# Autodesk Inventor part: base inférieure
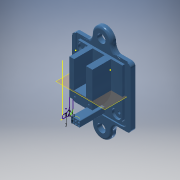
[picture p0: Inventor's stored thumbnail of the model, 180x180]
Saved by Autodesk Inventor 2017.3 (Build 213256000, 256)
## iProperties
Part Number: base inférieure
Material: Générique
Document SubType Name: Modeling
Designer: ficho
Density: 1 g/cm^3
Appearance: Pervenche
Author: ficho
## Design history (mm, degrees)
sketch "Esquisse1"
  geometry: L1 (4.5, -5.45)-(-4.5, -5.45) reference; L2 (4.5, 5.45)-(4.5, -5.45) reference; L3 (-4.5, 5.45)-(4.5, 5.45) reference; L4 (-4.5, -5.45)-(-4.5, 5.45) reference; L5 (-1.95, -7.7)-(4.55, -7.7) reference; L6 (-2.55, -9.12)-(-2.55, -8.3) reference; L7 (-2.096, -9.759)-(-2.308, -9.601) reference; L8 (-1.935, -10.8)-(-1.935, -10.08) reference; L9 (3.935, -11.4)-(-1.335, -11.4) reference; L10 (4.535, -10.08)-(4.535, -10.8) reference; L11 (4.908, -9.601)-(4.696, -9.759) reference; L12 (5.15, -8.3)-(5.15, -9.12) reference; L13 (-1.95, -8)-(4.55, -8) reference; L14 (4.85, -8.3)-(4.85, -9.12) reference; L15 (4.729, -9.361)-(4.517, -9.518) reference; L16 (4.235, -10.08)-(4.235, -10.8) reference; L17 (3.935, -11.1)-(-1.335, -11.1) reference; L18 (-1.635, -10.8)-(-1.635, -10.08) reference; L19 (-1.917, -9.518)-(-2.129, -9.361) reference; L20 (-2.25, -9.12)-(-2.25, -8.3) reference; L21 (-17.7, 15.45)-(20.2, 15.45); L22 (20.2, 15.45)-(20.2, -5.45); L23 (-17.7, -5.45)-(-17.7, 15.45); L24 (-5, -5.45)-(-17.7, -5.45); L25 (5, -5.45)-(20.2, -5.45); L26 (-5, -5.45)-(-5, 5.95); L27 (5, 5.95)-(5, -5.45); L28 (-5, 5.95)-(4.235, 5.95); L29 (4.5, 5.95)-(5, 5.95); L30 (-1.635, -5.95)-(-1.935, -5.95); L31 (-2.25, -5.95)-(-2.55, -5.95); L32 (5, -5.95)-(4.85, -5.95); L33 (4.535, -5.95)-(4.5, -5.95); L34 (4.5, 5.95)-(4.235, 5.95); C1 r 3.15 at (0, 0.95) reference; A1 r 0.6 centre (4.55, -8.3) between (5.15, -8.3) and (4.55, -7.7) reference; A2 r 0.6 centre (-1.95, -8.3) between (-1.95, -7.7) and (-2.55, -8.3) reference; A3 r 0.6 centre (-1.95, -9.12) between (-2.55, -9.12) and (-2.308, -9.601) reference; A4 r 0.4 centre (-2.335, -10.08) between (-1.935, -10.08) and (-2.096, -9.759) reference; A5 r 0.6 centre (-1.335, -10.8) between (-1.935, -10.8) and (-1.335, -11.4) reference; A6 r 0.6 centre (3.935, -10.8) between (3.935, -11.4) and (4.535, -10.8) reference; A7 r 0.4 centre (4.935, -10.08) between (4.696, -9.759) and (4.535, -10.08) reference; A8 r 0.6 centre (4.55, -9.12) between (4.908, -9.601) and (5.15, -9.12) reference; A9 r 0.3 centre (4.55, -8.3) between (4.85, -8.3) and (4.55, -8) reference; A10 r 0.3 centre (4.55, -9.12) between (4.729, -9.361) and (4.85, -9.12) reference; A11 r 0.7 centre (4.935, -10.08) between (4.517, -9.518) and (4.235, -10.08) reference; A12 r 0.3 centre (3.935, -10.8) between (3.935, -11.1) and (4.235, -10.8) reference; A13 r 0.3 centre (-1.335, -10.8) between (-1.635, -10.8) and (-1.335, -11.1) reference; A14 r 0.7 centre (-2.335, -10.08) between (-1.635, -10.08) and (-1.917, -9.518) reference; A15 r 0.3 centre (-1.95, -9.12) between (-2.25, -9.12) and (-2.129, -9.361) reference; A16 r 0.3 centre (-1.95, -8.3) between (-1.95, -8) and (-2.25, -8.3) reference; 3 further points
  constraints: 28 end point, 10 point on line, 2 perpendicular, 1 collinear, 1 horizontal, 1 parallel, 2 other
  dimensions: "d0" = 10 distance from line of point (-7.7, -6.45) L23; "d1" = 10 distance from line of L22 point (10.2, -6.45) (= d0); "d2" = 10 distance between parallel lines of L21 L3 (= d0); "d23" = 0.5 distance between parallel lines of L2 L27
  node "Référence1"
  node "Référence2"
node "Plan de construction1"
extrude "Extrusion1" new body sketch "Esquisse1" stored distance "d4" = 1; taper "d5" = 0 deg
sketch "Esquisse2"
  geometry: L1 (0, -20.9)-(15.2, -20.9) reference; L2 (25.34, -20.9)-(29.34, -20.9); L3 (29.34, -20.9)-(29.34, -4.794); L4 (29.34, -4.794)-(25.34, -4.794); L5 (25.34, -4.794)-(25.34, -20.9); L6 (9.7, -20.9)-(15.2, -20.9); L7 (15.2, -20.9)-(15.2, -4.794); L8 (15.2, -4.794)-(9.7, -4.794); L9 (9.7, -4.794)-(9.7, -20.9); 1 further point
  constraints: 16 end point, 4 parallel, 2 horizontal, 2 perpendicular
  dimensions: "d24" = 4 distance of L4.end L3.end
node "Plan de construction2"
extrude "Extrusion2" join sketch "Esquisse2" stored distance "d10" = 10; taper "d11" = 0 deg
sketch "Esquisse3"
  geometry: L1 (1.85, 0)-(31.85, 0) reference; L2 (1.85, 16.106)-(31.85, 16.106) reference; L3 (31.85, 0)-(24.85, 0); L4 (24.85, 0)-(24.85, 16.106); L5 (24.85, 16.106)-(31.85, 16.106); L6 (31.85, 16.106)-(31.85, 0); 1 further point
  constraints: 8 end point, 2 parallel, 1 horizontal, 1 perpendicular, 1 point on line
  dimensions: "d12" = 7 distance of L4.end L5.end
extrude "Extrusion3" join sketch "Esquisse3" stored distance "d13" = 10; taper "d14" = 0 deg
sketch "Esquisse4"
  geometry: C1 r 1.5 at (2.7, -28.92) reference; C2 r 1.5 at (-9.2, -28.92) reference; 1 further point
hole "Perçage1" sketch "Esquisse4" at (2.7, -28.92), (-9.2, -28.92) diameter "d15" = 1.5; stored, may be unused: countersink angle "d19" = 90 deg, drill point angle "d21" = 118 deg; dims "d16" = 6, "d17" = 4, "d18" = 2, "d20" = 8
fillet "Congé1" dims "d22" = 7
sketch "Esquisse5"
  geometry: L1 (12.7, 0)-(0, 0) reference; L2 (0, 0)-(37.9, 0); L3 (37.9, 0)-(37.9, 50); L4 (37.9, 50)-(0, 50); L5 (0, 50)-(0, 0); 1 further point
  constraints: 8 end point, 2 parallel, 1 horizontal, 1 perpendicular
  dimensions: "d25" = 50 distance of L3.end L2.end
extrude "Extrusion4" join sketch "Esquisse5" distance "d26" = 5; taper "d27" = 0 deg
sketch "Esquisse6"
  geometry: L1 (0, 0)-(37.9, 0) reference; L2 (0, 50)-(0, 0) reference; L3 (37.9, 0)-(37.9, 50) reference; L4 (37.9, 50)-(0, 50) reference; 3 further points
  dimensions: "d28" = 6 distance from line of point (4, 6) L1; "d29" = 4 distance from line of point (4, 6) L2; "d31" = 5 distance from line of L3 point (32.9, 40); "d32" = 10 distance from line of point (32.9, 40) L4
hole "Perçage2" sketch "Esquisse6" at (4, 6), (32.9, 40) diameter "d33" = 2.5; stored, may be unused: countersink angle "d37" = 90 deg, drill point angle "d39" = 118 deg; dims "d34" = 6, "d35" = 4, "d36" = 2, "d38" = 8
sketch "Esquisse7"
  geometry: L1 (37.9, 0)-(37.9, 50) reference; L2 (0, 50)-(0, 0) reference; L3 (0, 0)-(37.9, 0) reference; L4 (2.45, 0)-(35.45, 0); C1 r 3.5 at (18.95, -8); A1 r 8 centre (2.45, -8) between (10.45, -8) and (2.45, 0); A2 r 8 centre (35.45, -8) between (35.45, 0) and (27.45, -8); A3 r 8.5 centre (18.95, -8) between (10.45, -8) and (27.45, -8); 1 further point
  constraints: 6 point on circle, 4 centre point, 2 end point, 2 point on line, 2 tangent
  dimensions: "d40" = 18.95 distance from line of C1.centre L1; "d41" = 18.95 distance from line of C1.centre L2 (derived); "d42" = 8 distance from line of L3 C1.centre; "d43" = 7 diameter of C1; "d45" = 8 distance from line of L3 A2.centre (= d42); "d46" = 8 distance from line of L3 A1.centre (= d42)
extrude "Extrusion5" join sketch "Esquisse7" distance "d47" = 4; taper "d48" = 0 deg
fillet "Congé2" dims "d49" = 2
node "Plan de construction3"
mirror "Symétrie1"
mirror "Symétrie2"
sketch "Esquisse8"
  geometry: C1 r 1.25 at (4, -6) reference; C2 r 1.9 at (32.9, -40) reference; C3 r 2 at (4, -6) reference; C4 r 4 at (4, -6); C5 r 4 at (32.9, -40); 1 further point
  constraints: 2 centre point, 2 coincident
  dimensions: "d51" = 8 diameter of C4; "d52" = 8 diameter of C5 (= d51)
extrude "Extrusion6" cut sketch "Esquisse8" distance "d53" = 2; taper "d54" = 0 deg
sketch "Esquisse9"
  geometry: 1 further point
sketch "Esquisse11"
  geometry: L1 (0, 0)-(-1.85, 0) reference; L2 (0, 20.9)-(-50, 20.9) reference; L3 (0, 0)-(-1.85, 0); L4 (-1.85, 0)-(-1.85, 20.9); L5 (-1.85, 20.9)-(0, 20.9); L6 (0, 20.9)-(0, 0); 1 further point
  constraints: 8 end point, 2 parallel, 1 horizontal, 1 perpendicular, 1 point on line
extrude "Extrusion8" join sketch "Esquisse11" distance "d57" = 3; taper "d58" = 0 deg
sketch "Esquisse12"
  geometry: L1 (0, 5)-(48.15, 5) reference; L2 (0, 5)-(48.15, 5); L3 (48.15, 5)-(48.15, 2); L4 (48.15, 2)-(2, 2); L5 (0, 2)-(0, 5); L6 (44, 0)-(0, 0) reference; L7 (0, 0)-(2, 0); L8 (2, 0)-(2, 2); L9 (0, 2)-(0, 0); L10 (48.15, 5)-(48.15, -15.9) reference; 1 further point
  constraints: 14 end point, 3 parallel, 2 horizontal, 2 perpendicular, 1 collinear, 1 point on line
  dimensions: "d59" = 3 distance between parallel lines of L1 L4
extrude "Extrusion9" join sketch "Esquisse12" distance "d61" = 3; taper "d62" = 0 deg
sketch "Esquisse13"
  geometry: L1 (0, 0)-(0, 20.9) reference; L2 (-50, 20.9)-(-50, 15.9) reference; L3 (0, 16.895)-(-50, 16.895); L4 (-50, 16.895)-(-50, 20.9); L5 (-50, 20.9)-(0, 20.9); L6 (0, 20.9)-(0, 16.895); 1 further point
  constraints: 8 end point, 2 parallel, 1 horizontal, 1 perpendicular, 1 point on line
extrude "Extrusion10" join sketch "Esquisse13" distance "d63" = 3; taper "d64" = 0 deg
sketch "Esquisse14"
  geometry: L1 (42, 2)-(0, 2) reference; L2 (0, 0)-(3, 0); L3 (3, 0)-(3, 2); L4 (3, 2)-(0, 2); L5 (0, 2)-(0, 0); 1 further point
  constraints: 8 end point, 2 parallel, 1 horizontal, 1 perpendicular, 1 point on line
  dimensions: "d65" = 3 distance of L4.end L3.end
extrude "Extrusion11" cut sketch "Esquisse14" stored distance "d66" = 3; taper "d67" = 0 deg
sketch "Esquisse15"
  geometry: L1 (0, 18.9)-(0, 20.9) reference; L2 (0, 16.895)-(0, 20.9); L3 (0, 20.9)-(50, 20.9); L4 (50, 20.9)-(50, 17.9); L5 (1.85, 0)-(0, 0) reference; L6 (0, 0)-(1.85, 0); L7 (1.85, 0)-(1.85, 16.895); L8 (0, 16.895)-(0, 0); L9 (48, 17.9)-(1.85, 17.9); L10 (1.85, 16.895)-(1.85, 17.9); L11 (50, 16.895)-(50, 17.9); L12 (50, 20.9)-(50, 15.9) reference; L13 (48, 16.895)-(48, 17.9); L14 (50, 16.895)-(48, 16.895); 1 further point
  constraints: 22 end point, 3 perpendicular, 2 parallel, 1 collinear, 1 horizontal, 1 vertical
extrude "Extrusion12" join sketch "Esquisse15" distance "d68" = 3; taper "d69" = 0 deg
sketch "Esquisse16"
  geometry: L1 (50, 20.9)-(0, 20.9) reference; L2 (50, 16.895)-(0, 16.895); L3 (0, 16.895)-(0, 20.9); L4 (0, 20.9)-(50, 20.9); L5 (50, 20.9)-(50, 16.895); L6 (48, 16.895)-(50, 16.895) reference; 1 further point
  constraints: 8 end point, 2 parallel, 1 collinear, 1 horizontal, 1 perpendicular
extrude "Extrusion13" join sketch "Esquisse16" distance "d70" = 3 (= d63); taper "d71" = 0 deg
sketch "Esquisse17"
  geometry: L1 (-48, 16.895)-(-50, 16.895) reference; L2 (-50, 16.895)-(-50, 15.9) reference; L3 (-50, 15.9)-(-48, 15.9) reference; L4 (-48, 15.9)-(-48, 16.895) reference; 1 further point
extrude "Extrusion14" cut sketch "Esquisse17" stored distance "d72" = 3; taper "d73" = 0 deg
fillet "Congé3" dims "d74" = 3 (= d63)
sketch "Esquisse18"
  geometry: L1 (-1.85, 15.9)-(-1.85, 17.9) reference; L2 (-1.85, 17.9)-(1.15, 17.9); L3 (1.15, 17.9)-(1.15, 0); L4 (1.15, 0)-(-1.85, 0); L5 (-1.85, 0)-(-1.85, 17.9); 1 further point
  constraints: 8 end point, 2 parallel, 1 horizontal, 1 perpendicular
  dimensions: "d75" = 3 distance of L3.end L4.end
extrude "Extrusion15" cut sketch "Esquisse18" stored distance "d76" = 3; taper "d77" = 0 deg
sketch "Esquisse19"
  geometry: L1 (-13.15, -6)-(30.05, -6) reference; L2 (-13.15, -6)-(-13.15, -7.6) reference; L3 (0, 9.106)-(0, 0) reference; L4 (0, 0)-(-7.15, 0); L5 (-13.15, 0)-(-13.15, 0); L6 (-10.15, 3)-(0, 3); L7 (0, 3)-(0, 0); L8 (-13.15, -6)-(-10.15, -6); L9 (-10.15, -6)-(-10.15, -3); L10 (-10.15, 0)-(-13.15, 0); L11 (-13.15, 0)-(-13.15, -6); A1 r 3 centre (-7.15, -3) between (-7.15, 0) and (-10.15, -3); A2 r 3 centre (-10.15, 0) between (-10.15, 3) and (-13.15, 0); 1 further point
  constraints: 16 end point, 4 parallel, 4 point on circle, 4 tangent, 3 point on line, 2 centre point, 2 horizontal, 2 perpendicular, 1 equal radius
  dimensions: "d78" = 3 distance between parallel lines of L11 L9; "d79" = 3 distance between parallel lines of L6 L4 (= d78); "d80" = 3 radius of A1
  node "Référence6"
  node "Référence7"
sketch "Esquisse20"
  geometry: L1 (24.95, 8)-(24.95, 9.85) reference; L2 (24.95, 8)-(24.95, 6.839); L3 (24.95, 6.839)-(12.349, 6.839); L4 (-24.885, 6.839)-(-12.407, 6.839); L5 (-12.407, 6.839)-(-12.349, 6.839); L6 (-24.95, 8)-(-24.95, 55) reference; L7 (-24.95, 8)-(-24.95, 6.839); L8 (-24.95, 6.839)-(-24.885, 6.839); L9 (16.5, 8)-(24.95, 8) reference; L10 (24.95, 8)-(16.5, 8); L11 (-24.95, 8)-(-16.5, 8) reference; L12 (-24.95, 8)-(-16.5, 8); A1 r 8 centre (16.5, 0) between (16.5, 8) and (8.5, 0) reference; A2 r 8 centre (-16.5, 0) between (-8.5, 0) and (-16.5, 8) reference; A3 r 8 centre (16.5, 0) between (16.5, 8) and (12.349, 6.839); A4 r 8 centre (-16.5, 0) between (-12.349, 6.839) and (-16.5, 8); 2 further points
  constraints: 16 end point, 6 point on circle, 4 point on line, 3 collinear, 2 centre point, 2 concentric, 2 perpendicular, 1 vertical, 1 other
extrude "Extrusion16" join sketch "Esquisse20" stored distance "d81" = 10; taper "d82" = 0 deg
node "Plan de construction4"
sketch "Esquisse22"
  geometry: L1 (0, -45)-(37.9, -45) reference; L2 (3, -45)-(0, -45); L3 (0, -45)-(0, -42); L4 (37.9, -42)-(37.9, -45); L5 (37.9, -45)-(34.9, -45); A1 r 3 centre (3, -42) between (0, -42) and (3, -45) reference; A2 r 3 centre (34.9, -42) between (34.9, -45) and (37.9, -42) reference; 1 further point
  constraints: 8 end point, 3 tangent, 2 perpendicular, 1 collinear, 1 parallel, 1 point on line
extrude "Extrusion17" cut sketch "Esquisse22" stored distance "d84" = 10; taper "d85" = 0 deg
fillet "Congé4" dims "d86" = 3
node "Plan de construction5"
node "Plan de construction6"
sketch "Esquisse24"
  geometry: L1 (22.81, -40.323)-(22.81, -44.323) reference; L2 (15.19, -44.323)-(15.19, -40.323) reference; L3 (22.31, -39.823)-(15.69, -39.823); L4 (22.31, -44.823)-(15.69, -44.823); C1 r 0.9 at (19, -43.593) reference; C2 r 0.9 at (16.46, -43.593) reference; C3 r 0.9 at (16.46, -41.053) reference; C4 r 0.9 at (19, -41.053) reference; C5 r 0.9 at (21.54, -41.053) reference; C6 r 0.9 at (21.54, -43.593) reference; A1 r 0.5 centre (15.69, -44.323) between (15.19, -44.323) and (15.69, -44.823) reference; A2 r 0.5 centre (22.31, -44.323) between (22.31, -44.823) and (22.81, -44.323) reference; A3 r 0.5 centre (22.31, -40.323) between (22.81, -40.323) and (22.31, -39.823) reference; A4 r 0.5 centre (15.69, -40.323) between (15.69, -39.823) and (15.19, -40.323) reference; 1 further point
  constraints: 10 centre point, 8 end point, 8 point on circle, 2 vertical, 1 horizontal, 1 parallel, 1 tangent, 28 other
node "Plan de construction7"
extrude "Extrusion19" join sketch "Esquisse24" stored distance "d89" = 10; taper "d90" = 0 deg
fillet "Congé5" dims "d91" = 5.5
fillet "Congé6" dims "d92" = 5.5
sketch "Esquisse25"
  geometry: L1 (36.82, -3)-(33.82, -3) reference; L2 (33.809, -3.011)-(33.82, 0); L3 (36.82, -3.011)-(33.809, -3.011); L4 (-10.08, -3)-(-13.08, -3) reference; L5 (-10.08, -3)-(-10.08, 0.011); L6 (-10.08, -3)-(-13.08, -3) reference; L7 (-10.08, -3)-(-13.08, -3); L8 (-10.08, -3)-(-13.08, -3); A1 r 3.011 centre (33.809, -3.011) between (36.82, -3.011) and (33.82, 0) reference; A2 r 3 centre (-10.08, -3) between (-10.08, 0) and (-13.08, -3); 1 further point
  constraints: 10 end point, 4 point on circle, 2 centre point, 2 horizontal, 1 coincident, 1 collinear, 1 point on line, 1 vertical, 4 other
extrude "Extrusion20" join sketch "Esquisse25" stored distance "d93" = 10; taper "d94" = 0 deg
node "Solide1"
node "Référence3"
node "Référence4"
node "Référence5"
node "Boucle projetée1"
node "Référence8"
node "Référence9"
other parameters: "d44" = 5, "d50" = -25
